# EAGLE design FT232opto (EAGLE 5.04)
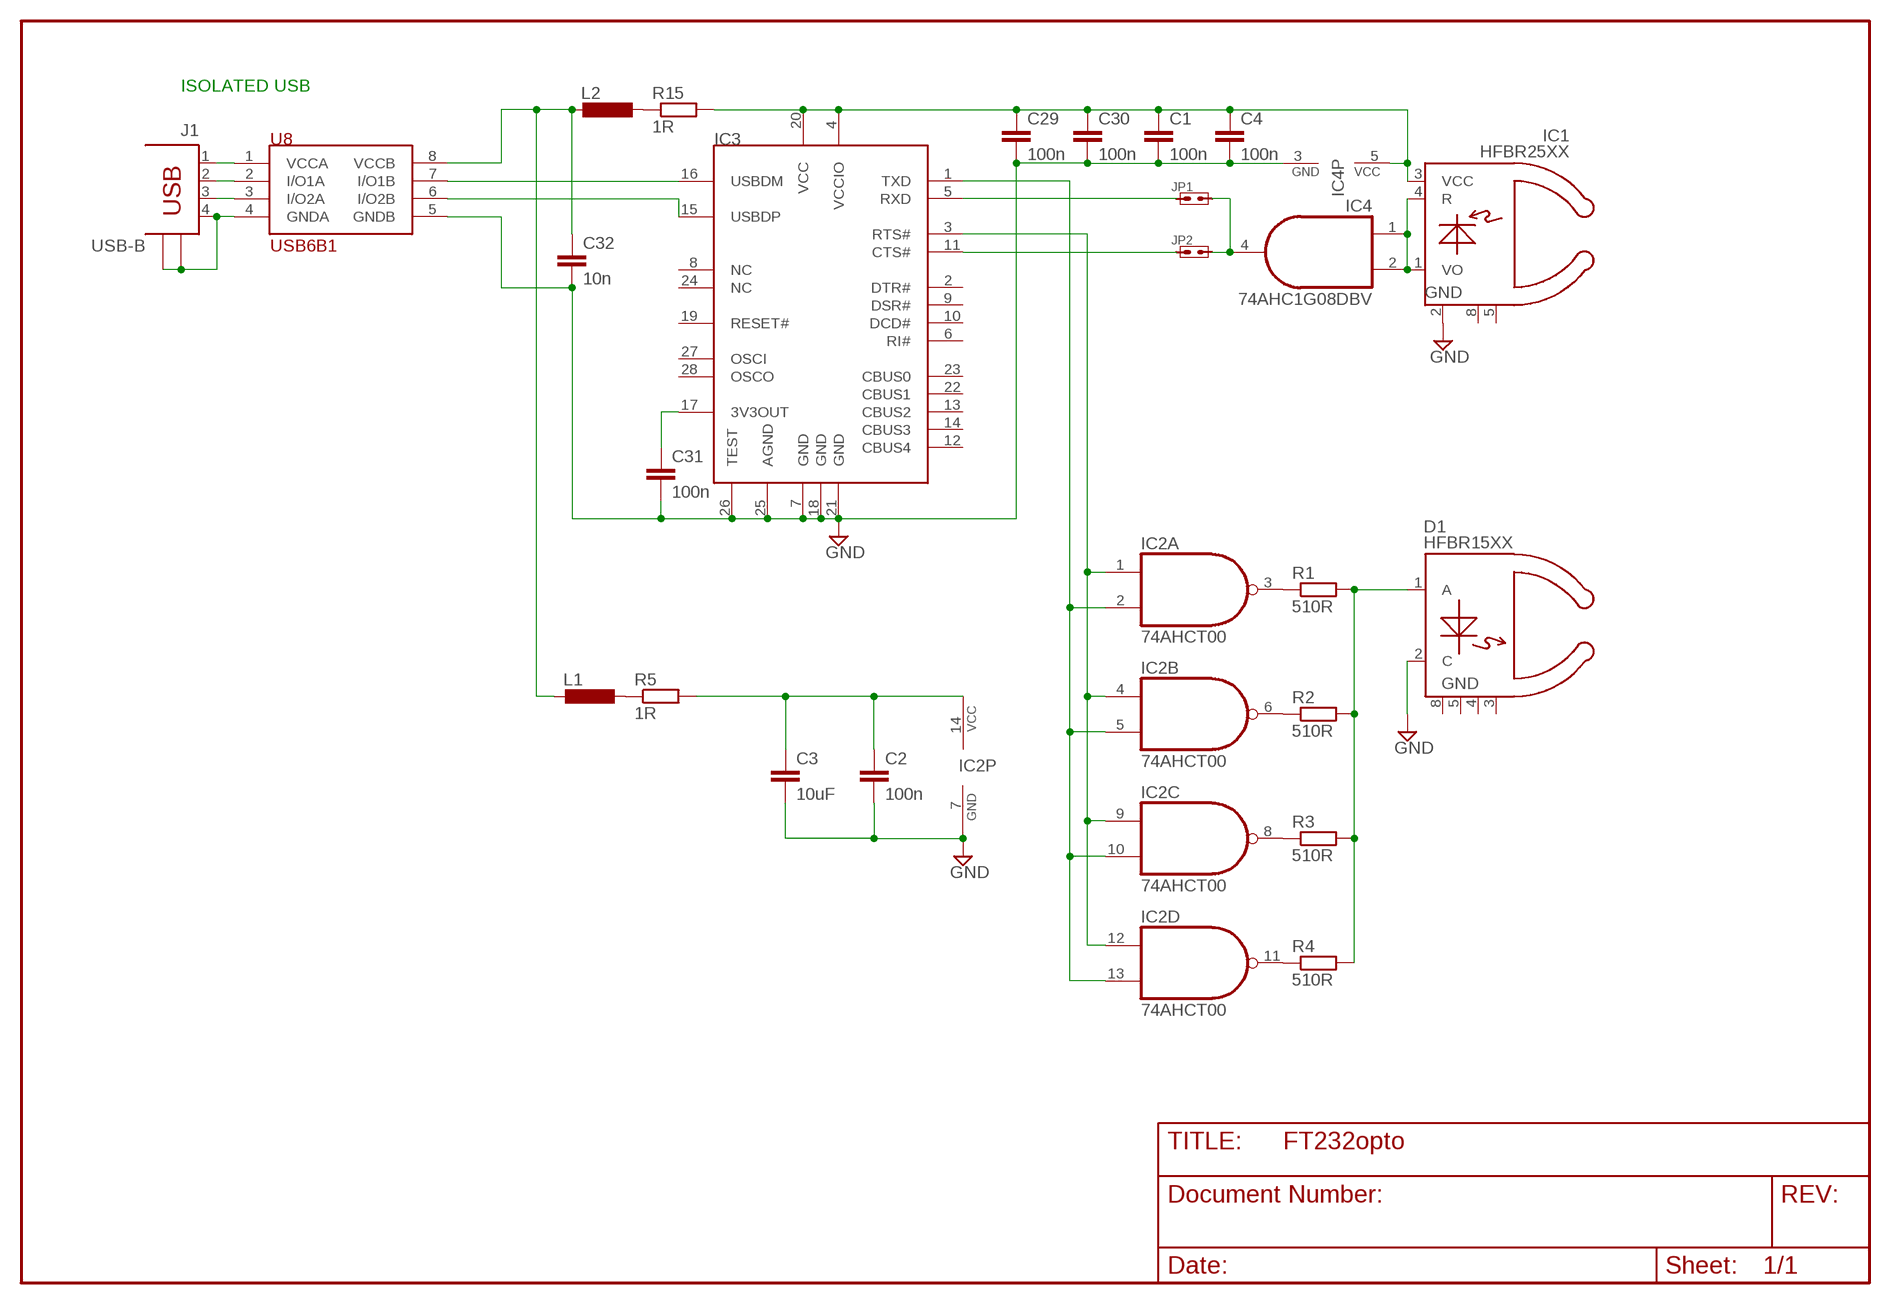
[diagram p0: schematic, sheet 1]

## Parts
C1  100n  C0805  [C0805]
C2  100n  C0805  [C0805]
C3  10uF  C0805  [C0805]
C4  100n  C0805  [C0805]
C29  100n  C0805  [C0805]
C30  100n  C0805  [C0805]
C31  100n  C0805  [C0805]
C32  10n  C0805  [C0805]
D1  HFBR15XX  [HFBR25XX]
IC1  HFBR25XX  [HFBR25XX]
IC2  74AHCT00  74LS00D  [SO14]
IC3  FT232RL  [SSOP28]
IC4  74AHC1G08DBV  [SOT23-5]
J1  USB-B  [USBCONNB]
JP1  JMP2  [JP2]
JP2  JMP2  [JP2]
L1  L0805  [R0805]
L2  L0805  [R0805]
R1  510R  R1206  [R1206]
R2  510R  R1206  [R1206]
R3  510R  R1206  [R1206]
R4  510R  R1206  [R1206]
R5  1R  R0805  [R0805]
R15  1R  R0805  [R0805]
U8  USB6B1  [SO8]

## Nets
GND: C1.1 C2.1 C3.1 C4.1 C29.1 C30.1 C31.1 C32.1 D1.2(C) IC1.2(GND) IC2.7(P:GND) IC3.7(GND) IC3.18(GND) IC3.21(GND) IC3.25(AGND) IC3.26(TEST) IC4.3(GND) U8.5(GNDB)
N$1: IC4.4(O) JP1.2 JP2.2
N$2: IC3.5(RXD) JP1.1
N$3: IC3.11(CTS#) JP2.1
N$4: IC2.1(A:I0) IC2.4(B:I0) IC2.9(C:I0) IC2.12(D:I0) IC3.3(RTS#)
N$5: IC2.2(A:I1) IC2.5(B:I1) IC2.10(C:I1) IC2.13(D:I1) IC3.1(TXD)
N$6: IC2.3(A:O) R1.1
N$7: IC2.6(B:O) R2.1
N$8: IC2.8(C:O) R3.1
N$9: IC2.11(D:O) R4.1
N$10: IC3.16(USBDM) U8.7(I/O1B)
N$11: J1.1 U8.1(VCCA)
N$12: D1.1(A) R1.2 R2.2 R3.2 R4.2
N$13: IC1.1(VO) IC1.4(R) IC4.1(I0) IC4.2(I1)
N$14: C2.2 C3.2 IC2.14(P:VCC) R5.2
N$16: L1.2 R5.1
N$28: C31.2 IC3.17(3V3OUT)
N$29: J1.4 J1.CASE@1(CASE) J1.CASE@2(CASE) U8.4(GNDA)
N$32: IC3.15(USBDP) U8.6(I/O2B)
N$33: C1.2 C4.2 C29.2 C30.2 IC1.3(VCC) IC3.4(VCCIO) IC3.20(VCC) IC4.5(VCC) R15.2
N$34: J1.3 U8.3(I/O2A)
N$35: J1.2 U8.2(I/O1A)
N$36: C32.2 L1.1 L2.1 U8.8(VCCB)
N$37: L2.2 R15.1
Unconnected: D1.3 D1.4 D1.5(GND) D1.8(GND) IC1.5 IC1.8 IC3.2(DTR#) IC3.6(RI#) IC3.8(NC) IC3.9(DSR#) IC3.10(DCD#) IC3.12(CBUS4) IC3.13(CBUS2) IC3.14(CBUS3) IC3.19(RESET#) IC3.22(CBUS1) IC3.23(CBUS0) IC3.24(NC) IC3.27(OSCI) IC3.28(OSCO)

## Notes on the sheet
- ISOLATED USB

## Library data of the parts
C1-C4 C29-C32 = NoiseRLC:C: Capacitor
D1 = Zoli:HFBR15XX: OPTO TRANSMITTER
IC1 = Zoli:HFBR25XX: Opto receiver
IC2 = 74xx-us:74*00: Quad 2-input NAND gate
IC3 = Zoli:FT232RL
IC4 = 74xx-little-us:74*1G08: 2-input AND gate
J1 = Zoli:USB-B
JP1 JP2 = Zoli:JMP2
L1 L2 = NoiseRLC:L: Inductance
R1-R4 = Zoli:R: Resistor
R5 R15 = NoiseRLC:R: Resistor
U8 = Zoli:USB6B1: USB channel protector

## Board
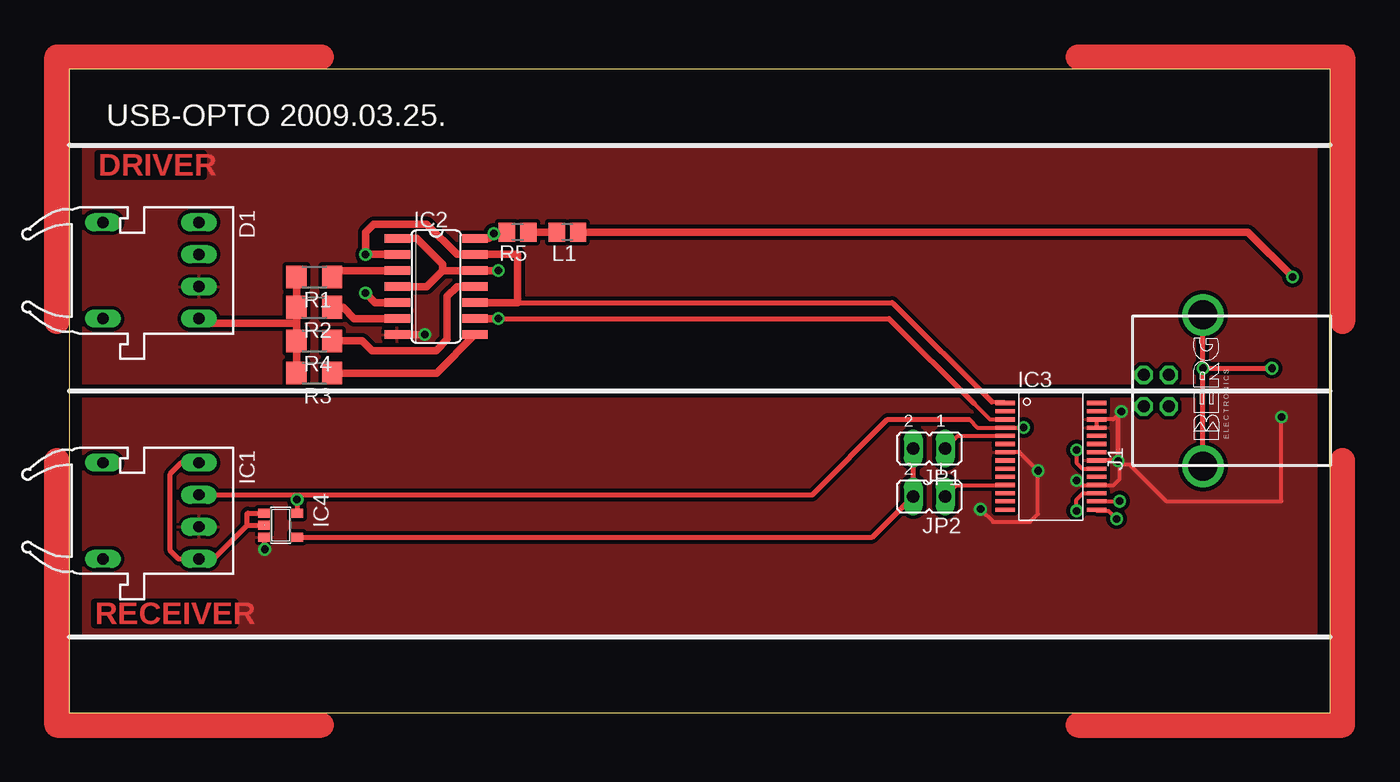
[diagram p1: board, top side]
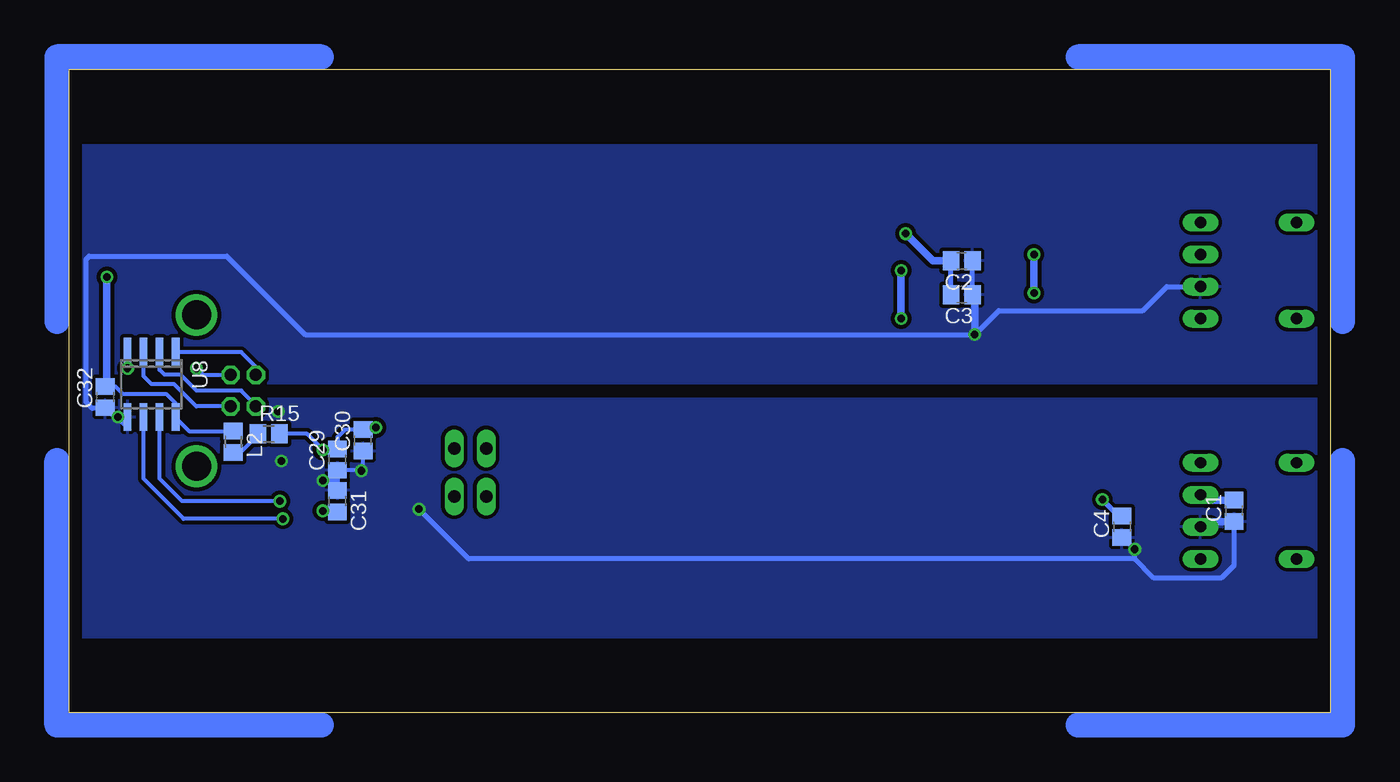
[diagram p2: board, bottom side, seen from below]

Size 100 x 51 mm. Coordinates in mm from the lower left corner, seen from the top.
Outline: 0,0 100,0 100,51 0,51 0,0
Copper layers (1*16): Top 0.035mm / dielectric 1.5mm / Bottom 0.035mm
Design rules "default *": minimum track width 8mil, minimum drill 16mil, track to track 5mil, track to pad 5mil, pad to pad 5mil, via to via 5mil, smd to smd 0mil, copper to edge 40mil, drill to drill 8mil, minimum pad ring 10mil, minimum via ring 8mil, stop-mask expansion 4mil, vias tented up to drill 0mil, thermal gap 10mil
tRestrict: 1 lines
bRestrict: 1 lines

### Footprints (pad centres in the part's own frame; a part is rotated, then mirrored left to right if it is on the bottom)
C0805 = smd 1.3 x 1.5: 1 -0.85,0; 2 0.85,0
HFBR25XX = drill 0.9 long: 1 0,3.81; 2 0,1.27; 3 0,-1.27; 4 0,-3.81; 5 7.62,-3.81; 8 7.62,3.81
SO14 = smd 0.66 x 2.032: 1 -3.81,-3.073; 2 -2.54,-3.073; 3 -1.27,-3.073; 4 0,-3.073; 5 1.27,-3.073; 6 2.54,-3.073; 7 3.81,-3.073; 8 3.81,3.073; 9 2.54,3.073; 10 1.27,3.073; 11 0,3.073; 12 -1.27,3.073; 13 -2.54,3.073; 14 -3.81,3.073
SSOP28 = smd 0.33 x 1.524: 1 -4.225,-3.625; 2 -3.575,-3.625; 3 -2.925,-3.625; 4 -2.275,-3.625; 5 -1.625,-3.625; 6 -0.975,-3.625; 7 -0.325,-3.625; 8 0.325,-3.625; 9 0.975,-3.625; 10 1.625,-3.625; 11 2.275,-3.625; 12 2.925,-3.625; 13 3.575,-3.625; 14 4.225,-3.625; 15 4.225,3.625; 16 3.575,3.625; 17 2.925,3.625; 18 2.275,3.625; 19 1.625,3.625; 20 0.975,3.625; 21 0.325,3.625; 22 -0.325,3.625; 23 -0.975,3.625; 24 -1.625,3.625; 25 -2.275,3.625; 26 -2.925,3.625; 27 -3.575,3.625; 28 -4.225,3.625
SOT23-5 = smd 0.69 x 0.99: 1 -0.95,-1.29; 2 0,-1.29; 3 0.95,-1.29; 4 0.95,1.3; 5 -0.95,1.3
USBCONNB = drill 0.95 octagon: 1 1.25,4.71; 2 -1.25,4.71; 3 -1.25,2.71; 4 1.25,2.71 | drill 2.3 round: CASE@1 -6,0; CASE@2 6,0
JP2 = drill 1 long: 1 -1.27,0; 2 1.27,0
R0805 = smd 1.3 x 1.5: 1 -0.85,0; 2 0.85,0
R1206 = smd 1.6 x 1.803: 1 -1.422,0; 2 1.422,0
SO8 = smd 0.6 x 2.2: 1 -1.905,-2.6; 2 -0.635,-2.6; 3 0.635,-2.6; 4 1.905,-2.6; 5 1.905,2.6; 6 0.635,2.6; 7 -0.635,2.6; 8 -1.905,2.6

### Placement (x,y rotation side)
C1  7.62,16 90 bottom
C2  29.21,35.81 180 bottom
C3  29.21,33.15 180 bottom
C4  16.51,14.73 90 bottom
C29  78.74,20.07 90 bottom
C30  76.71,21.59 90 bottom
C31  78.74,16.76 270 bottom
C32  97.16,25.02 90 bottom
D1  10.29,35.05 180 top
IC1  10.29,16 180 top
IC2  29.08,33.78 270 top
IC3  77.85,20.32 270 top
IC4  16.76,14.86 270 top
J1  89.92,25.53 90 top
JP1  68.2,20.95 180 top
JP2  68.2,17.14 180 top
L1  39.5,38.1 180 top
L2  87,21.46 270 bottom
R1  19.43,34.54 180 top
R2  19.43,32.13 180 top
R3  19.43,26.92 180 top
R4  19.43,29.46 180 top
R5  35.56,38.1 180 top
R15  84.2,22.1 0 bottom
U8  93.47,26.04 180 bottom

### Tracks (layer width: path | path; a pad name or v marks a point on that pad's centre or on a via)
GND  (via drill 0.6)
  Top 0.305: IC3.21 83.13,20 v83.19,19.94 83.31,19.81 83.31,19.68 | IC3.25 81.52,22.59 81.53,22.61 81.48,22.66 IC3.26 81.41,23.25 81.41,23.24 82.8,23.24 v83.44,23.88 | 83.31,19.68 83.31,18.54 82.81,18.05 IC3.18 80.25,18.05 v79.88,18.41 | 83.31,19.68 84.07,19.68 87,16.76 96.14,16.76 v96.14,23.43 | v72.26,16.13 73.28,15.11 76.2,15.11 76.83,15.75 v76.83,19.18 75.37,20.64 IC3.7
  Top 0.406: v83.19,19.94 83.19,23.62 v83.44,23.88 | IC4.3 15.47,12.97 v15.49,12.95
  Top 0.61: v28.19,29.97 IC2.7
  Bottom 0.305: C32.1 97.16,24.13 96.46,23.43 v96.14,23.43 U8.5 | 78.74,18.41 v79.88,18.41 | 78.74,18.41 C29.1 76.87,19.22 v76.83,19.18 76.71,19.3 C30.1 | 78.74,18.41 C31.1
  Bottom 0.406: 96.21,23.43 96.27,23.5 | v96.14,23.43 96.21,23.43 | 96.21,23.43 95.38,22.61 | D1.2 12.95,33.78 14.86,31.88 26.29,31.88 v28.19,29.97 81.28,29.97 87.5,36.2 98.42,36.2 98.68,35.94 98.68,24.64 98.17,24.13 97.19,24.13 C32.1 | C3.1 C2.1 | v72.26,16.13 68.33,12.19 15.49,12.19 | 15.49,12.19 13.97,10.67 8.64,10.67 7.62,11.68 C1.1 | 15.49,12.19 v15.49,12.95 16.51,13.97 16.76,13.97
  Bottom 0.61: v28.19,29.97 28.19,32.98 C3.1 | C1.1 9.87,15.15 IC1.2
  pour Bottom (isolate 0.305): 0.13,5.97 0.13,44.96 99.95,44.96 99.95,25.02 99.89,6
  pour Top (isolate 0.305): 0.13,44.96 100.02,44.88 100.02,6.64 100.08,6.1 6.1,6.1 6.1,5.97 0.13,5.97
N$1
  Top 0.406: JP1.2 JP2.2 63.69,13.91 IC4.4
N$2
  Top 0.305: IC3.5 70.46,21.95 JP1.1
N$3
  Top 0.305: IC3.11 70.37,18.05 JP2.1
N$4  (via drill 0.6)
  Top 0.305: IC3.3 73.02,23.25 71.75,24.51
  Top 0.406: 71.75,24.51 65.02,31.24 v34.04,31.24
  Top 0.61: IC2.4 28.32,33.78 29.59,35.05 | 29.59,35.05 IC2.12 v34.04,35.05 | IC2.1 27.56,37.59 29.59,35.56 29.59,35.05 | v34.04,31.24 IC2.9
  Bottom 0.61: v34.04,35.05 v34.04,31.24
N$5  (via drill 0.6)
  Top 0.305: 73.15,24.64 74.13,24.64 IC3.1
  Top 0.406: 35.56,32.51 65.28,32.51 73.15,24.64
  Top 0.61: IC2.10 35.56,32.51 35.56,36.32 IC2.13 30.73,36.32 28.32,38.73 24.13,38.73 23.5,38.1 v23.5,36.32 IC2.2 | IC2.5 24.26,32.51 v23.5,33.27
  Bottom 0.61: v23.5,33.27 v23.5,36.32
N$6
  Top 0.61: IC2.3 21.36,35.05 R1.1
N$7
  Top 0.61: IC2.6 22.61,31.24 21.72,32.13 R2.1
N$8
  Top 0.61: R3.1 29.11,26.92 IC2.8
N$9
  Top 0.61: R4.1 23.24,29.46 24,28.7 29.08,28.7 29.97,29.59 29.97,33.02 30.73,33.78 IC2.11
N$10  (via drill 0.6)
  Top 0.305: IC3.16 81.52,16.75 81.53,16.76 v83.31,16.76
  Bottom 0.305: U8.7 92.84,18.54 91.06,16.76 v83.31,16.76
N$11
  Bottom 0.305: U8.1 91.57,28.57 86.36,28.57 85.21,27.42 85.22,27.42 J1.1
N$12
  Top 0.61: R1.2 R2.2 18.01,30.73 | R4.2 R3.2 | 18.01,30.73 R4.2 | R4.2 17.88,29.34 | D1.1 10.67,30.86 17.88,30.86 18.01,30.73
N$13
  Top 0.406: IC1.4 8.89,19.81 8,18.92 8,12.83 8.64,12.19 IC1.1 11.43,12.19 14.1,14.86 | 14.1,14.86 IC4.2 | IC4.1 14.16,15.81 14.1,15.75 14.1,14.86
N$14  (via drill 0.6)
  Top 0.61: R5.2 34.58,37.97 v33.66,37.97 33.27,37.59 IC2.14
  Bottom 0.406: C3.2 C2.2
  Bottom 0.61: C2.2 31.5,35.81 v33.66,37.97
N$16
  Top 0.61: R5.1 L1.2
N$28  (via drill 0.6)
  Top 0.305: IC3.17 80.39,17.39 79.88,16.89 v79.88,16
  Bottom 0.305: C31.2 78.74,16 v79.88,16
N$29  (via drill 0.6)
  Top 0.305: J1.CASE@2 89.92,31.62
  Top 0.406: v89.92,27.3 v95.38,27.3 | v89.92,27.3 J1.CASE@2 | J1.CASE@1 v89.92,27.3
  Bottom 0.305: v89.92,27.3 89.39,26.78 87.25,26.78 | 95.38,28.7 U8.4 v95.38,27.3 | 87.25,26.78 J1.4 | 87.25,26.78 87.25,26.8
N$32  (via drill 0.6)
  Top 0.305: v83.06,15.37 82.42,16 81.53,16 81.48,16.06 IC3.15
  Bottom 0.305: U8.6 94.11,18.54 90.93,15.37 v83.06,15.37
N$33  (via drill 0.6)
  Top 0.305: IC3.20 80.35,19.34 79.88,19.81 v79.88,20.83 | v75.69,22.61 75.68,22.59 IC3.4 72.02,22.59 71.37,23.24
  Top 0.406: IC1.3 18.16,17.27 | 18.16,17.27 58.93,17.27 64.9,23.24 71.37,23.24 | IC4.5 v18.06,16.89 18.06,16.92 18.16,17.27
  Bottom 0.305: C29.2 78.65,20.92 78.61,20.95 78.57,20.92 | C29.2 79.8,20.92 v79.88,20.83 81.15,22.1 R15.2 | C29.2 78.74,21.84 78.14,22.44 C30.2 76.54,22.61 v75.69,22.61
  Bottom 0.406: C4.2 16.75,15.58 v18.06,16.89
  Bottom 0.61: C1.2 9.87,16.85 IC1.3
N$34
  Bottom 0.305: U8.3 94.11,26.67 93.47,26.04 91.69,26.04 89.94,24.28 87.25,24.28 | J1.3 87.25,24.28 | 87.25,24.28 87.25,24.26
N$35
  Bottom 0.305: U8.2 92.84,27.18 92.46,26.8 91.19,26.8 89.92,25.53 86.36,25.53 85.21,24.37 85.22,24.37 J1.2 | J1.2 | J1.2 85.22,24.26
N$36  (via drill 0.6)
  Top 0.61: L1.1 93.47,38.1 v97.03,34.54
  Bottom 0.305: C32.2 96.35,25.87 95.76,25.27 92.33,25.27 91.57,24.51 U8.8 91.57,23.37 90.51,22.31 L2.1
  Bottom 0.61: v97.03,34.54 97.03,26 C32.2
N$37
  Bottom 0.305: R15.1 85.05,22.01 86.45,20.61 L2.2
N$91
  Top 2: 20,-1 -1,-1 -1,20
N$92
  Top 2: 80,-1 101,-1 101,20
N$93
  Top 2: 20,52 -1,52 -1,31
N$94
  Top 2: 101,31 101,52 80,52
N$95
  Bottom 2: 20,-1 -1,-1 -1,20
N$96
  Bottom 2: 80,-1 101,-1 101,20
N$97
  Bottom 2: 20,52 -1,52 -1,31
N$98
  Bottom 2: 101,31 101,52 80,52

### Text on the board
Top: DRIVER | RECEIVER
tPlace: USB-OPTO 2009.03.25.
